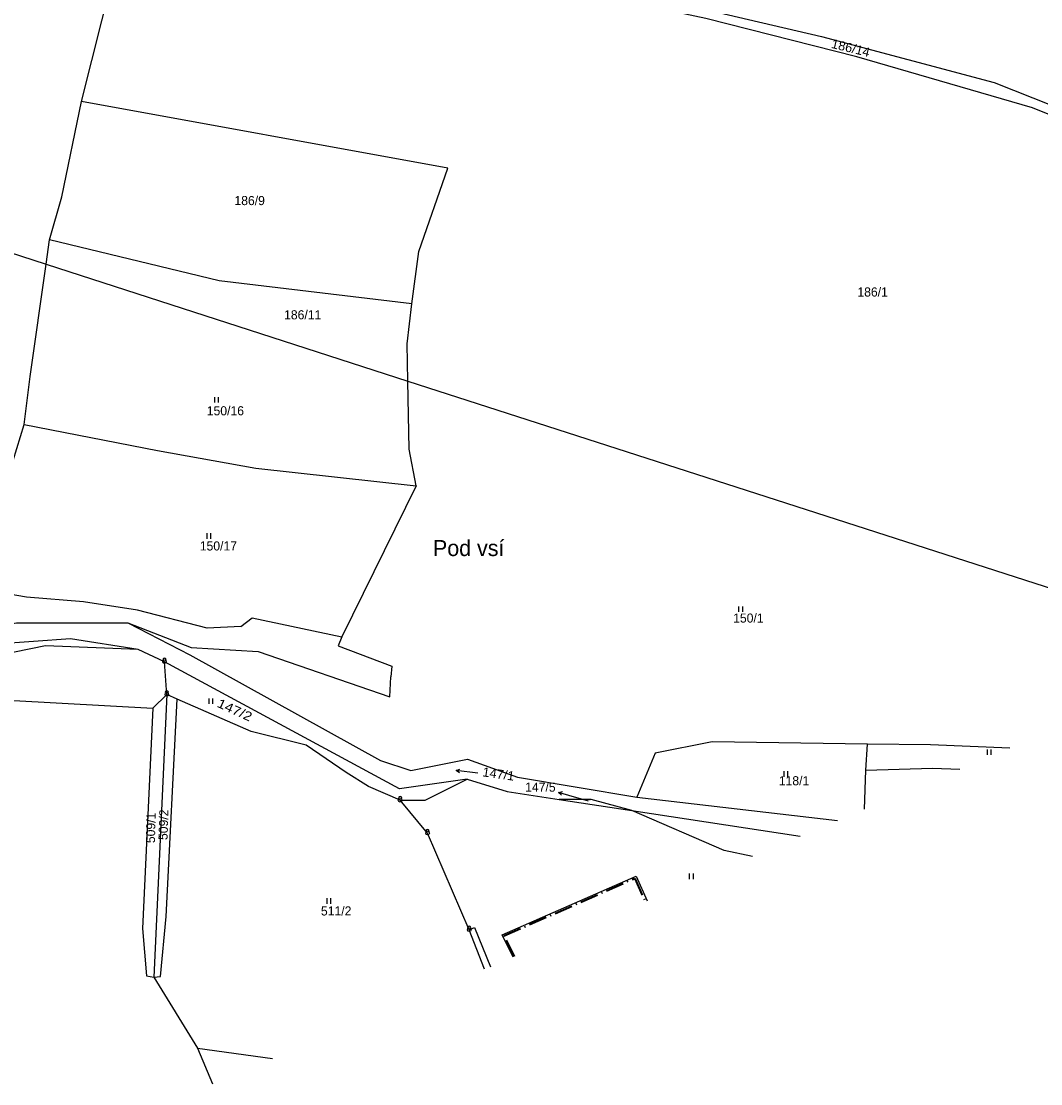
# Model space of a CAD drawing. Extents: x -680102 to -677253, y -1007548 to -1006096.
# Drawn here: x -678877.9 to -678597.9, y -1007258.2 to -1006966.4 of the extents above; entities that cross this region are included whole.
import ezdxf
from ezdxf.enums import TextEntityAlignment as Align

# ---------------------------------------------------------------- set-up
doc = ezdxf.new("R2010")
doc.units = 0
doc.linetypes.add('DOT_DASHED', pattern=[7.7, 5, -1.2, 0.3, -1.2])
for name, color, linetype, lineweight in [('1', 7, 'Continuous', 25), ('13', 7, 'Continuous', 25), ('16', 7, 'Continuous', 25), ('24', 7, 'Continuous', 25), ('25', 7, 'Continuous', 25), ('5', 7, 'DOT_DASHED', 35)]:
    doc.layers.add(name, color=color, linetype=linetype, lineweight=lineweight)
doc.layers.add('15', color=7, linetype='Continuous')
doc.layers.add('18', color=7, linetype='Continuous')

msp = doc.modelspace()

# ---------------------------------------------------------------- linework, layer by layer
at = {"layer": '1'}
for p, q in [((-678771.73, -1007065.25), (-678662.27, -1007100.49)), ((-678769.4, -1007093.94), (-678771.36, -1007083.87)), ((-678662.27, -1007100.49), (-678553.82, -1007135.42)), ((-678848.59, -1007131.59), (-678831.24, -1007138.36)), ((-678831.24, -1007138.36), (-678812.79, -1007139.46)), ((-678831.62, -1007140.39), (-678779.18, -1007169.39)), ((-678812.79, -1007139.46), (-678776.61, -1007151.94)), ((-678776.61, -1007151.94), (-678776.4, -1007146.39)), ((-678838.13, -1007212.26), (-678835.05, -1007152.53)), ((-678606.31, -1007165.99), (-678628.13, -1007165.14)), ((-678779.18, -1007169.39), (-678770.89, -1007172.19)), ((-678741.62, -1007174.04), (-678708.85, -1007179.49)), ((-678645.94, -1007172.03), (-678627.58, -1007171.56)), ((-678627.58, -1007171.56), (-678620.06, -1007171.78)), ((-678744.46, -1007177.94), (-678730.11, -1007180.13)), ((-678708.85, -1007179.49), (-678653.68, -1007185.93)), ((-678730.11, -1007180.13), (-678710.2, -1007183.17)), ((-678721.35, -1007180.13), (-678730.11, -1007180.13)), ((-678710.2, -1007183.17), (-678663.93, -1007190.23)), ((-678663.93, -1007190.23), (-678663.91, -1007190.23)), ((-678677.05, -1007195.76), (-678684.81, -1007194.14)), ((-678829.5, -1007248.43), (-678825.39, -1007258.21)), ((-678829.5, -1007248.43), (-678808.87, -1007251.26))]:
    msp.add_line(p, q, dxfattribs=at)
for points in [[(-678870.13, -1007026.39), (-678866.73, -1007014.59), (-678861.38, -1006988.42), (-678852.96, -1006954.87), (-678877.65, -1006956.32), (-678890.58, -1006957.9), (-678914.35, -1006963.48), (-678934.64, -1006970.99), (-678950.61, -1006977.53), (-678960.58, -1006983.85)], [(-678428.42, -1007058.52), (-678456.65, -1007048.79), (-678480.7, -1007039.81), (-678505.2, -1007028.21), (-678600.16, -1006990.16), (-678648.38, -1006976.17), (-678689.83, -1006965.56), (-678727.06, -1006957.66), (-678741.11, -1006957.27)], [(-678700.9, -1006960.54), (-678658.05, -1006970.53), (-678610.61, -1006983.2)], [(-678610.61, -1006983.2), (-678589.4, -1006991.58), (-678556.93, -1007004.42)], [(-678770.6, -1007043.94), (-678768.7, -1007029.59), (-678760.69, -1007006.73), (-678861.38, -1006988.42)], [(-678963.41, -1007003.12), (-678871.07, -1007033.05), (-678771.73, -1007065.25)], [(-678875.46, -1007063.95), (-678871.07, -1007033.05), (-678870.13, -1007026.39)], [(-678771.93, -1007054.97), (-678770.6, -1007043.94), (-678823.52, -1007037.67), (-678870.13, -1007026.39)], [(-678771.36, -1007083.87), (-678771.73, -1007065.25), (-678771.93, -1007054.97)], [(-678893.52, -1007121.58), (-678883.92, -1007098.59), (-678881.12, -1007090.34), (-678877.08, -1007077.12), (-678875.46, -1007063.95)], [(-678877.08, -1007077.12), (-678840.5, -1007084.23), (-678813.44, -1007089.09), (-678769.4, -1007093.94), (-678789.85, -1007135.49)], [(-678876.46, -1007124.51), (-678893.52, -1007121.58), (-678944.16, -1007126.17)], [(-678817.54, -1007132.57), (-678826.8, -1007133.09), (-678845.98, -1007128.12), (-678860.81, -1007125.87), (-678876.46, -1007124.51)], [(-678817.54, -1007132.57), (-678814.44, -1007130.26), (-678789.85, -1007135.49), (-678790.85, -1007137.88), (-678776.14, -1007143.5), (-678776.4, -1007146.39)], [(-678976.98, -1007147.88), (-678961.76, -1007145.67), (-678942.37, -1007145.27), (-678929.35, -1007143.41), (-678891.54, -1007133.71), (-678879.24, -1007131.57), (-678848.59, -1007131.59), (-678831.62, -1007140.39)], [(-678845.78, -1007138.92), (-678864.4, -1007136.04), (-678894.96, -1007138.23)], [(-678755.43, -1007174.58), (-678774.02, -1007177.2), (-678838.55, -1007142.27)], [(-679006.75, -1007210.69), (-678984.84, -1007202.32), (-678982.94, -1007197.98), (-678966.55, -1007193.65), (-678929.85, -1007162), (-678913.15, -1007157.35), (-678879.91, -1007152.9), (-678841.8, -1007155.02), (-678837.91, -1007151.27)], [(-678837.91, -1007151.27), (-678841.47, -1007228.94), (-678829.5, -1007248.43)], [(-678841.8, -1007155.02), (-678844.58, -1007215.54), (-678843.53, -1007228.57), (-678841.47, -1007228.94), (-678839.61, -1007228.78), (-678838.13, -1007212.26)], [(-678688.08, -1007164.26), (-678703.81, -1007167.38), (-678708.85, -1007179.49)], [(-678628.13, -1007165.14), (-678645.41, -1007164.89), (-678688.08, -1007164.26)], [(-678646.26, -1007182.81), (-678645.94, -1007172.03), (-678645.41, -1007164.89)], [(-678770.89, -1007172.19), (-678755.36, -1007169.05), (-678741.62, -1007174.04)], [(-678773.82, -1007180.33), (-678766.97, -1007180.28), (-678755.43, -1007174.58), (-678744.46, -1007177.94)], [(-678684.81, -1007194.14), (-678710.2, -1007183.17), (-678721.35, -1007180.13)], [(-678742.8, -1007223.44), (-678745.77, -1007217.35), (-678709.01, -1007201.15), (-678706.01, -1007207.96)], [(-678754.85, -1007215.9), (-678753.37, -1007215.33), (-678749.02, -1007226.06)]]:
    msp.add_lwpolyline(points, dxfattribs=at)
at = {"layer": '13'}
for p, q in [((-678837.91, -1007151.27), (-678838.55, -1007142.27)), ((-678799.65, -1007165.22), (-678814.73, -1007161.47)), ((-678788.63, -1007172.71), (-678799.65, -1007165.22)), ((-678782.53, -1007176.56), (-678788.63, -1007172.71)), ((-678773.82, -1007180.33), (-678782.53, -1007176.56)), ((-678766.3, -1007189.36), (-678773.82, -1007180.33)), ((-678754.85, -1007215.9), (-678766.3, -1007189.36)), ((-678750.63, -1007226.74), (-678754.85, -1007215.9))]:
    msp.add_line(p, q, dxfattribs=at)
for points in [[(-678838.55, -1007142.27), (-678845.78, -1007138.92), (-678871.25, -1007137.96), (-678879.8, -1007139.67), (-678898.95, -1007140.53), (-678928.07, -1007147.86)], [(-678814.73, -1007161.47), (-678835.05, -1007152.53), (-678837.91, -1007151.27)]]:
    msp.add_lwpolyline(points, dxfattribs=at)
at = {"layer": '16'}
for p, q in [((-678727.44, -1007179.01), (-678730.32, -1007178.174)), ((-678722.05, -1007180.57), (-678727.44, -1007179.01))]:
    msp.add_line(p, q, dxfattribs=at)
msp.add_lwpolyline([(-678729.5, -1007178.933), (-678730.32, -1007178.174), (-678729.221, -1007177.972)], dxfattribs=at)
at = {"layer": '24'}
for centre, radius in [((-678838.55, -1007142.27), 0.5), ((-678838.55, -1007142.27), 0.022), ((-678837.91, -1007151.27), 0.5), ((-678837.91, -1007151.27), 0.022), ((-678773.82, -1007180.33), 0.5), ((-678773.82, -1007180.33), 0.022), ((-678766.3, -1007189.36), 0.5), ((-678766.3, -1007189.36), 0.022), ((-678754.85, -1007215.9), 0.5), ((-678754.85, -1007215.9), 0.022)]:
    msp.add_circle(centre, radius, dxfattribs=at)
for centre in [(-678838.551, -1007141.707), (-678837.911, -1007150.707), (-678773.821, -1007179.767), (-678766.301, -1007188.797), (-678754.851, -1007215.337)]:
    msp.add_arc(centre, 0.437, 328.35109, 209.97456, dxfattribs=at)
at = {"layer": '25'}
for p, q in [((-678824.717, -1007071.115), (-678824.717, -1007069.615)), ((-678823.683, -1007071.115), (-678823.683, -1007069.615)), ((-678826.857, -1007108.505), (-678826.857, -1007107.005)), ((-678825.823, -1007108.505), (-678825.823, -1007107.005)), ((-678680.747, -1007128.585), (-678680.747, -1007127.085)), ((-678679.713, -1007128.585), (-678679.713, -1007127.085)), ((-678826.277, -1007153.875), (-678826.277, -1007152.375)), ((-678825.243, -1007153.875), (-678825.243, -1007152.375)), ((-678612.487, -1007167.865), (-678612.487, -1007166.365)), ((-678611.453, -1007167.865), (-678611.453, -1007166.365)), ((-678752.514, -1007172.915), (-678758.466, -1007172.165)), ((-678668.347, -1007173.885), (-678668.347, -1007172.385)), ((-678667.313, -1007173.885), (-678667.313, -1007172.385)), ((-678694.297, -1007201.985), (-678694.297, -1007200.485)), ((-678693.263, -1007201.985), (-678693.263, -1007200.485)), ((-678793.857, -1007208.745), (-678793.857, -1007207.245)), ((-678792.823, -1007208.745), (-678792.823, -1007207.245))]:
    msp.add_line(p, q, dxfattribs=at)
msp.add_lwpolyline([(-678757.536, -1007172.785), (-678758.466, -1007172.165), (-678757.411, -1007171.794)], dxfattribs=at)
at = {"layer": '5'}
msp.add_line((-678742.42, -1007223.28), (-678745.22, -1007217.6), dxfattribs=at)
msp.add_lwpolyline([(-678745.3, -1007217.6), (-678709.39, -1007201.82), (-678706.5, -1007208.16)], dxfattribs=at)

# ---------------------------------------------------------------- texts
at = {"layer": '15'}
msp.add_text('Pod vsí', height=4.4, dxfattribs=at).set_placement((-678754.99, -1007113.26), align=Align.CENTER)
at = {"layer": '16'}
msp.add_text('147/5', height=2.5, dxfattribs=at).set_placement((-678731.12, -1007177.98), align=Align.RIGHT)
at = {"layer": '18'}
for s, rotation, width, p in [('186/14', 346.303, 1.05, (-678655.589, -1006973.634)), ('147/2', 335.503, 1.2, (-678824.336, -1007154.591)), ('147/1', 352.003, 1.05, (-678751.325, -1007173.75))]:
    msp.add_text(s, height=2.5, rotation=rotation, dxfattribs=dict(at, width=width)).set_placement(p)
for s, height, p in [('186/9', 2.5, (-678819.34, -1007016.86)), ('186/1', 2.5, (-678648.22, -1007041.97)), ('186/11', 2.5, (-678805.7, -1007048.24)), ('150/16', 2.5, (-678826.94, -1007074.6)), ('150/17', 2.5, (-678828.86, -1007111.73)), ('150/1', 2.5, (-678682.35, -1007131.54)), ('118/1', 2.5, (-678669.81, -1007176.23)), ('147/5', 0.1, (-678721.85, -1007180.37)), ('511/2', 2.5, (-678795.58, -1007211.99))]:
    msp.add_text(s, height=height, dxfattribs=at).set_placement(p)
msp.add_text('509/1', height=2.5, rotation=88.701, dxfattribs=at).set_placement((-678841.083, -1007187.958), align=Align.CENTER)
msp.add_text('509/2', height=2.5, rotation=88.201, dxfattribs=at).set_placement((-678837.723, -1007191.284))

doc.saveas('drawing.dxf')
